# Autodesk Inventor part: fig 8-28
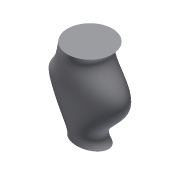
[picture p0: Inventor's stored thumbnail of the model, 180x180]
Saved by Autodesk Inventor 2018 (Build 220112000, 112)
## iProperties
Shininess: 64.0
Length Units: 11269
Angle Units: 11279
Time Units: 11290
Mass Units: 11283
Length Display Precision: 3
Angle Display Precision: 2
Compacted: True
Part Number: fig 8-28
Document SubType Name: Modeling
Created: 2002-12
Designer: deepak
Density: 1 g/cm^3
Material: Generic
Appearance: Default
Density: 0.0
Volumn: 0.0
Area: 0.0
PropertySet Name: Model Information
Control State: 0
Master: False
Checked Out: False
Author: deepak
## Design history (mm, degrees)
sketch "Sketch1"
  geometry: 2 further points; 1 other entity
  constraints: 1 coincident, 3 other
workplane "Work Plane1"
workplane "Work Plane2"
sketch "Sketch3"
  geometry: C1 r 60 at (0, 0); 1 further point
  constraints: 1 centre point, 1 coincident, 1 other
sketch "Sketch4"
  geometry: 8 further points
  constraints: 8 other
sketch "Sketch5"
  geometry: 6 further points
  constraints: 6 other
sketch "Sketch6"
  geometry: 6 further points
  constraints: 6 other
  dimensions: "d20" = 35 distance of point (0, 0) point (-35, 0); "d21" = 0 vertical distance of point (0, 0) point (-35, 0); "d22" = 225 vertical distance of point (0, 0) point (-60, 225); "d23" = 60 horizontal distance of point (0, 0) point (-60, 225); "d24" = 100 horizontal distance of point (0, 0) point (-100, 125); "d25" = 125 vertical distance of point (0, 0) point (-100, 125)
loft "Loft5" dims "d54" = 0, "d55" = 90 deg, "d56" = 0, "d57" = 90 deg, "d58" = 0, "d59" = 90 deg, "d60" = 0, "d61" = 90 deg
body "Solid2"
other parameters: "d5" = 125
